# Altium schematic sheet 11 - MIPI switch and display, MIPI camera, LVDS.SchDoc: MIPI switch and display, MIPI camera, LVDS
size A3; PageSetup: Record=PageOptions¦CenterHorizontal=True¦CenterVertical=True¦PrintScale=0.70¦XCorrection=1.00¦YCorrection=1.00¦PrintKind=0¦BorderSize=5000000¦LeftOffset=0¦BottomOffset=0¦Orientation=2¦PaperLength=4200¦PaperWidth=2970¦Scale=100¦PaperSource=7¦PrintQuality=600¦MediaType=1¦DitherType=10¦PaperKind=A4¦PrintScaleMode=1; Author: Juan Anzola; SheetNumber: 11; SheetTotal: 20
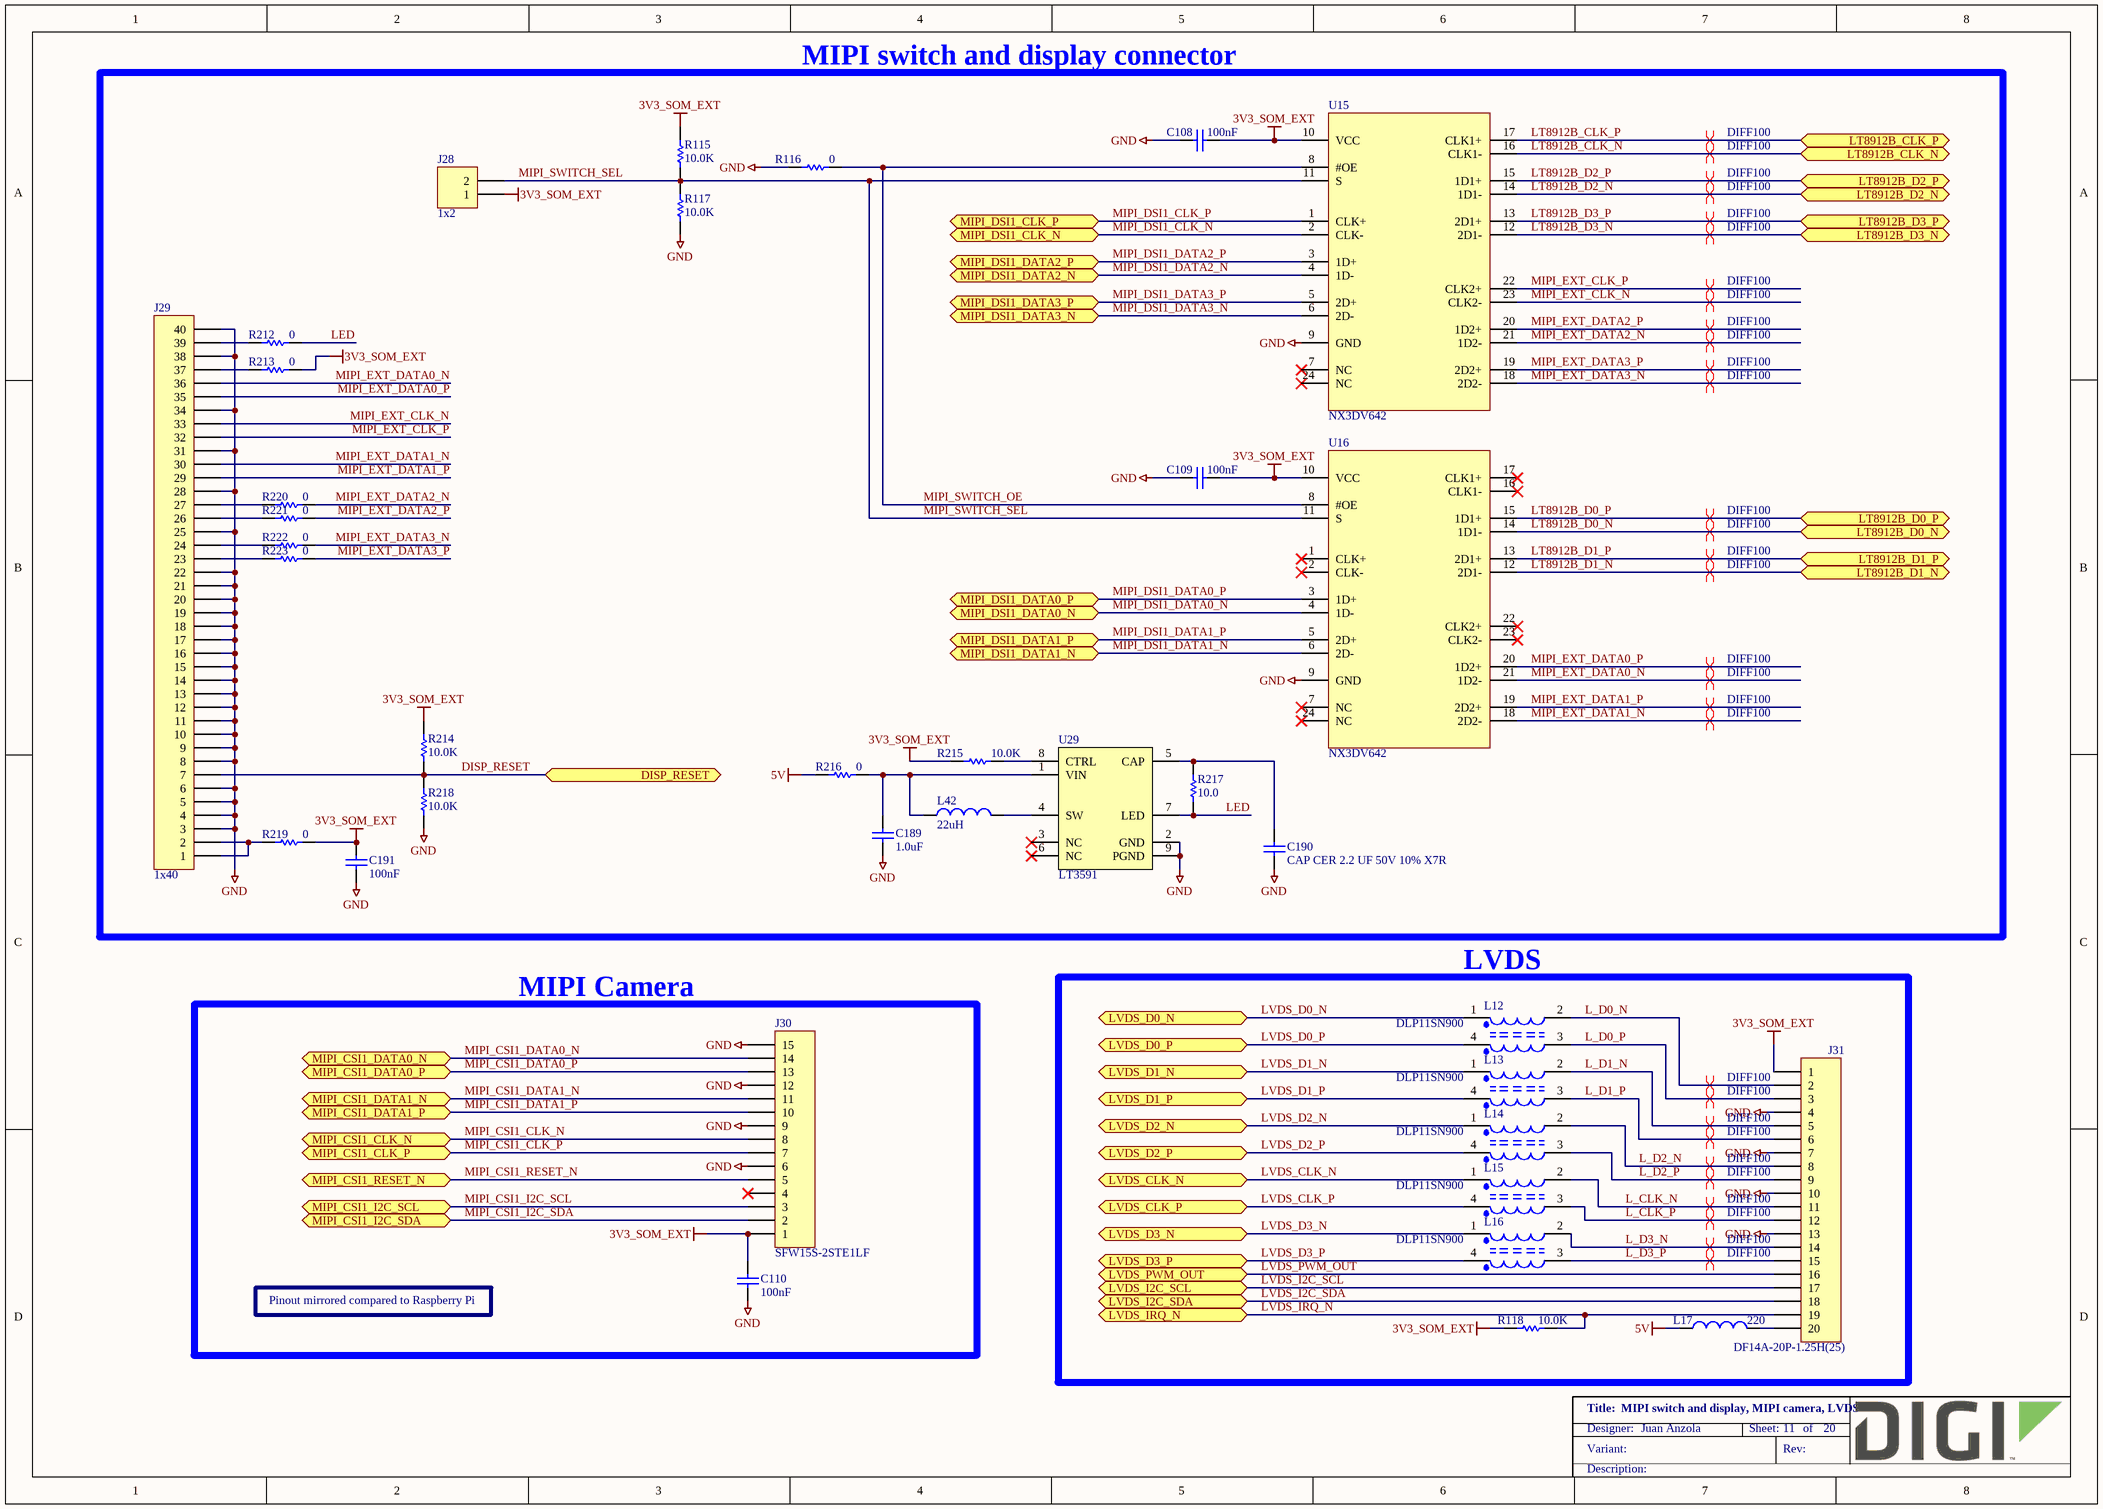
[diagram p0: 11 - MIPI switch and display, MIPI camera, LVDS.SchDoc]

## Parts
C108  100nF  [CAPC1005X55N]
C109  100nF  [CAPC1005X55N]
C110  100nF  [CAPC1005X55N]
C189  1.0uF  [CAPC1005X55N]
C190  CAP CER 2.2 UF 50V 10% X7R  [CAPC3225X250N]
C191  100nF  [CAPC1005X55N]
J28  1x2  [FCI_68002-102HLF]
J29  1x40  [OMRON_XF2M-4015-1A]
J30  SFW15S-2STE1LF  [FCI_SFW15S-2STE1LF]
J31  DF14A-20P-1.25H(25)  [HIROSE_DF14A-20P-1.25H]
L12  DLP11SN900  [FIL_DLP11S]
L13  DLP11SN900  [FIL_DLP11S]
L14  DLP11SN900  [FIL_DLP11S]
L15  DLP11SN900  [FIL_DLP11S]
L16  DLP11SN900  [FIL_DLP11S]
L17  220  [INDC2013X110N]
L42  22uH  [IND_NR4018T220M]
R115  10.0K  [RESC1005X40N]
R116  0  [RESC1609X55N]
R117  10.0K  [RESC1005X40N]
R118  10.0K  [RESC1005X40N]
R212  0  [RESC1005X40N]
R213  0  [RESC1005X40N]
R214  10.0K  [RESC1005X40N]
R215  10.0K  [RESC1005X40N]
R216  0  [RESC1005X40N]
R217  10.0  [RESC1005X40N]
R218  10.0K  [RESC1005X40N]
R219  0  [RESC1005X40N]
R220  0  [RESC1005X40N]
R221  0  [RESC1005X40N]
R222  0  [RESC1005X40N]
R223  0  [RESC1005X40N]
U15  NX3DV642  [QFN40P340X250X50-24N]
U16  NX3DV642  [QFN40P340X250X50-24N]
U29  LT3591  [SON50P300X200X80-9T56X215N]

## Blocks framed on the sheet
MIPI switch and display connector: C108 C109 C189-C191 J28 J29 L42 R115-R117 R212-R223 U15 U16 U29
LVDS: J31 L12-L17 R118
MIPI Camera: C110 J30

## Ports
DISP_RESET (bidir), LT8912B_CLK_N (bidir), LT8912B_CLK_P (bidir), LT8912B_D0_N (bidir), LT8912B_D0_P (bidir), LT8912B_D1_N (bidir), LT8912B_D1_P (bidir), LT8912B_D2_N (bidir), LT8912B_D2_P (bidir), LT8912B_D3_N (bidir), LT8912B_D3_P (bidir), LVDS_CLK_N (bidir), LVDS_CLK_P (bidir), LVDS_D0_N (bidir), LVDS_D0_P (bidir), LVDS_D1_N (bidir), LVDS_D1_P (bidir), LVDS_D2_N (bidir), LVDS_D2_P (bidir), LVDS_D3_N (bidir), LVDS_D3_P (bidir), LVDS_I2C_SCL (bidir), LVDS_I2C_SDA (bidir), LVDS_IRQ_N (bidir), LVDS_PWM_OUT (bidir), MIPI_CSI1_CLK_N (bidir), MIPI_CSI1_CLK_P (bidir), MIPI_CSI1_DATA0_N (bidir), MIPI_CSI1_DATA0_P (bidir), MIPI_CSI1_DATA1_N (bidir), MIPI_CSI1_DATA1_P (bidir), MIPI_CSI1_I2C_SCL (bidir), MIPI_CSI1_I2C_SDA (bidir), MIPI_CSI1_RESET_N (bidir), MIPI_DSI1_CLK_N (bidir), MIPI_DSI1_CLK_P (bidir), MIPI_DSI1_DATA0_N (bidir), MIPI_DSI1_DATA0_P (bidir), MIPI_DSI1_DATA1_N (bidir), MIPI_DSI1_DATA1_P (bidir), MIPI_DSI1_DATA2_N (bidir), MIPI_DSI1_DATA2_P (bidir), MIPI_DSI1_DATA3_N (bidir), MIPI_DSI1_DATA3_P (bidir)

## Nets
3V3_SOM_EXT: C108.1 C109.1 C110.2 C191.2 J28.1 J30.1 J31.1 R115.1 R118.1 R213.2 R214.1 R215.1 R219.2 U15.10(VCC) U16.10(VCC)
5V: L17.1 R216.1
GND: C108.2 C109.2 C110.1 C189.1 C190.1 C191.1 J29.3 J29.4 J29.5 J29.6 J29.8 J29.9 J29.10 J29.11 J29.12 J29.13 J29.14 J29.15 J29.16 J29.17 J29.18 J29.19 J29.20 J29.21 J29.22 J29.25 J29.28 J29.31 J29.34 J29.38 J29.40 J30.6 J30.9 J30.12 J30.15 J31.4 J31.7 J31.10 J31.13 R116.1 R117.2 R218.2 U15.9(GND) U16.9(GND) U29.2(GND) U29.9(PGND)
DISP_RESET: J29.7 R214.2 R218.1 ; port DISP_RESET
L_CLK_N: J31.11 L15.2
L_CLK_P: J31.12 L15.3
L_D0_N: J31.2 L12.2
L_D0_P: J31.3 L12.3
L_D1_N: J31.5 L13.2
L_D1_P: J31.6 L13.3
L_D2_N: J31.8 L14.2
L_D2_P: J31.9 L14.3
L_D3_N: J31.14 L16.2
L_D3_P: J31.15 L16.3
LED: R212.2 R217.1 U29.7(LED)
LT8912B_CLK_N: U15.16(CLK1-) ; port LT8912B_CLK_N
LT8912B_CLK_P: U15.17(CLK1+) ; port LT8912B_CLK_P
LT8912B_D0_N: U16.14(1D1-) ; port LT8912B_D0_N
LT8912B_D0_P: U16.15(1D1+) ; port LT8912B_D0_P
LT8912B_D1_N: U16.12(2D1-) ; port LT8912B_D1_N
LT8912B_D1_P: U16.13(2D1+) ; port LT8912B_D1_P
LT8912B_D2_N: U15.14(1D1-) ; port LT8912B_D2_N
LT8912B_D2_P: U15.15(1D1+) ; port LT8912B_D2_P
LT8912B_D3_N: U15.12(2D1-) ; port LT8912B_D3_N
LT8912B_D3_P: U15.13(2D1+) ; port LT8912B_D3_P
LVDS_CLK_N: L15.1 ; port LVDS_CLK_N
LVDS_CLK_P: L15.4 ; port LVDS_CLK_P
LVDS_D0_N: L12.1 ; port LVDS_D0_N
LVDS_D0_P: L12.4 ; port LVDS_D0_P
LVDS_D1_N: L13.1 ; port LVDS_D1_N
LVDS_D1_P: L13.4 ; port LVDS_D1_P
LVDS_D2_N: L14.1 ; port LVDS_D2_N
LVDS_D2_P: L14.4 ; port LVDS_D2_P
LVDS_D3_N: L16.1 ; port LVDS_D3_N
LVDS_D3_P: L16.4 ; port LVDS_D3_P
LVDS_I2C_SCL: J31.17 ; port LVDS_I2C_SCL
LVDS_I2C_SDA: J31.18 ; port LVDS_I2C_SDA
LVDS_IRQ_N: J31.19 R118.2 ; port LVDS_IRQ_N
LVDS_PWM_OUT: J31.16 ; port LVDS_PWM_OUT
MIPI_CSI1_CLK_N: J30.8 ; port MIPI_CSI1_CLK_N
MIPI_CSI1_CLK_P: J30.7 ; port MIPI_CSI1_CLK_P
MIPI_CSI1_DATA0_N: J30.14 ; port MIPI_CSI1_DATA0_N
MIPI_CSI1_DATA0_P: J30.13 ; port MIPI_CSI1_DATA0_P
MIPI_CSI1_DATA1_N: J30.11 ; port MIPI_CSI1_DATA1_N
MIPI_CSI1_DATA1_P: J30.10 ; port MIPI_CSI1_DATA1_P
MIPI_CSI1_I2C_SCL: J30.3 ; port MIPI_CSI1_I2C_SCL
MIPI_CSI1_I2C_SDA: J30.2 ; port MIPI_CSI1_I2C_SDA
MIPI_CSI1_RESET_N: J30.5 ; port MIPI_CSI1_RESET_N
MIPI_DSI1_CLK_N: U15.2(CLK-) ; port MIPI_DSI1_CLK_N
MIPI_DSI1_CLK_P: U15.1(CLK+) ; port MIPI_DSI1_CLK_P
MIPI_DSI1_DATA0_N: U16.4(1D-) ; port MIPI_DSI1_DATA0_N
MIPI_DSI1_DATA0_P: U16.3(1D+) ; port MIPI_DSI1_DATA0_P
MIPI_DSI1_DATA1_N: U16.6(2D-) ; port MIPI_DSI1_DATA1_N
MIPI_DSI1_DATA1_P: U16.5(2D+) ; port MIPI_DSI1_DATA1_P
MIPI_DSI1_DATA2_N: U15.4(1D-) ; port MIPI_DSI1_DATA2_N
MIPI_DSI1_DATA2_P: U15.3(1D+) ; port MIPI_DSI1_DATA2_P
MIPI_DSI1_DATA3_N: U15.6(2D-) ; port MIPI_DSI1_DATA3_N
MIPI_DSI1_DATA3_P: U15.5(2D+) ; port MIPI_DSI1_DATA3_P
MIPI_EXT_CLK_N: J29.33 U15.23(CLK2-)
MIPI_EXT_CLK_P: J29.32 U15.22(CLK2+)
MIPI_EXT_DATA0_N: J29.36 U16.21(1D2-)
MIPI_EXT_DATA0_P: J29.35 U16.20(1D2+)
MIPI_EXT_DATA1_N: J29.30 U16.18(2D2-)
MIPI_EXT_DATA1_P: J29.29 U16.19(2D2+)
MIPI_EXT_DATA2_N: R220.2 U15.21(1D2-)
MIPI_EXT_DATA2_P: R221.2 U15.20(1D2+)
MIPI_EXT_DATA3_N: R222.2 U15.18(2D2-)
MIPI_EXT_DATA3_P: R223.2 U15.19(2D2+)
MIPI_SWITCH_OE: R116.2 U15.8(#OE) U16.8(#OE)
MIPI_SWITCH_SEL: J28.2 R115.2 R117.1 U15.11(S) U16.11(S)
NetC189_2: C189.2 L42.1 R216.2 U29.1(VIN)
NetC190_2: C190.2 R217.2 U29.5(CAP)
NetJ29_1: J29.1 J29.2 R219.1
NetJ29_23: J29.23 R223.1
NetJ29_24: J29.24 R222.1
NetJ29_26: J29.26 R221.1
NetJ29_27: J29.27 R220.1
NetJ29_37: J29.37 R213.1
NetJ29_39: J29.39 R212.1
NetJ31_20: J31.20 L17.2
NetL42_2: L42.2 U29.4(SW)
NetR215_2: R215.2 U29.8(CTRL)

Not connected (* = marked no-connect by the designer): J30 4*; U15 7(NC)* 24(NC)*; U16 1(CLK+)* 2(CLK-)* 7(NC)* 16(CLK1-)* 17(CLK1+)* 22(CLK2+)* 23(CLK2-)* 24(NC)*; U29 3(NC)* 6(NC)*

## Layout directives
differential pair; net class DIFF100; differential pair class DIFF100: L_CLK_N, L_CLK_P, L_D0_N, L_D0_P, L_D1_N, L_D1_P, L_D2_N, L_D2_P, L_D3_N, L_D3_P, LT8912B_CLK_N, LT8912B_CLK_P, LT8912B_D0_N, LT8912B_D0_P, LT8912B_D1_N, LT8912B_D1_P, LT8912B_D2_N, LT8912B_D2_P, LT8912B_D3_N, LT8912B_D3_P, MIPI_EXT_CLK_N, MIPI_EXT_CLK_P, MIPI_EXT_DATA0_N, MIPI_EXT_DATA0_P, MIPI_EXT_DATA1_N, MIPI_EXT_DATA1_P, MIPI_EXT_DATA2_N, MIPI_EXT_DATA2_P, MIPI_EXT_DATA3_N, MIPI_EXT_DATA3_P

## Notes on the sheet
- Pinout mirrored compared to Raspberry Pi

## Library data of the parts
C108-C110 = 1000006: CAP 100nF 16V 10% X7R 0402; Part_Type: Capacitor; Manufacturer: Murata; Manufacturer_Part_Number: GRM155R71C104KA88D; Digi_PN: 14050552; Component_Life_Cycle_State: CAD Reviewed; Area: 0,95; Project: KITT; Tolerance: 10
C189 = 1001167: CAP CER 1UF 10V 10% X5R 0402; Part_Type: Capacitor; Manufacturer: Murata; Manufacturer_Part_Number: GRM155R61A105KE15D; Digi_PN: 14050399; Component_Life_Cycle_State: Reviewed; Area: 0,95
C190 = 1002042: 2.2µF ±10% 50V X7R Ceramic Capacitor -55°C ~ 125°C Surface Mount, MLCC 1210 (3225 Metric) 0.126" L x 0.098" W (3.20mm x 2.50mm); Manufacturer: AVX; Manufacturer_Part_Number: 12105C225KAT2A; Digi_PN: 14050578; Component_Life_Cycle_State: Created; Area: 8
C191 = 1000006: CAP 100nF 16V 10% X7R 0402; Part_Type: Capacitor; Manufacturer: Murata; Manufacturer_Part_Number: GRM155R71C104KA88D; Digi_PN: 14050552; Component_Life_Cycle_State: CAD Reviewed; Area: 0,95; Tolerance: 10
J28 = 1001128: CONN HEADER 2POS .100" SGL GOLD; Part_Type: Connector; Manufacturer: Samtec; Manufacturer_Part_Number: TSW-102-07-G-S; Digi_PN: 00120002; Component_Life_Cycle_State: Reviewed; Area: 12,9032
J29 = 1001144: CONN FPC 40POS 0.5MM PITCH SMD; Part_Type: Connector; Manufacturer: Omron; Manufacturer_Part_Number: XF2M-4015-1A; Digi_PN: 18000676; Component_Life_Cycle_State: Reviewed; Area: 117,5
J30 = 1001866: CONN FFC FPC VERT 15POS 1MM SMD; Part_Type: Connector; Manufacturer: FCI; Digi_PN: 18000730; Component_Life_Cycle_State: Reviewed; Area: 128,76; Project: CCiMX6 SBC MFG TEST BOARD
J31 = 1001132: CONN HEADER 20POS 1.25MM R/A SMD; Part_Type: Connector; Manufacturer: Hirose; Digi_PN: 18050231; Component_Life_Cycle_State: Reviewed; Area: 206.34; Project: CCWMX6_SBC board
L12-L16 = 1001014: CHOKE COIL COMMON MODE 150MA SMD; Part_Type: Inductor; Manufacturer: Murata; Manufacturer_Part_Number: DLP11SN900HL2L; Component_Life_Cycle_State: Reviewed; Area: 3.94; Project: ResMed RF Test Interface Board; Digi_PN: 21000531
L17 = 1001174: FERRITE BEAD 220 OHM 2.0A 0805; Manufacturer: Wurth Electronics Inc; Manufacturer_Part_Number: 742792022; Digi_PN: 21000146; Component_Life_Cycle_State: Reviewed; Area: 4.24; Project: CCWMX6_SBC board
L42 = 1002050: FIXED IND 22UH 590MA 432 MOHM; Manufacturer: Taiyo Yuden; Manufacturer_Part_Number: NR4018T220M; Digi_PN: 21000545; Component_Life_Cycle_State: Created; Area: 16
R115 R117 R215 = 1000537: RES 10.0K OHM 1/10W 1% 0402 SMD; Part_Type: Resistor; Manufacturer: Panasonic - ECG; Manufacturer_Part_Number: ERJ-2RKF1002X; Digi_PN: 13051084; Component_Life_Cycle_State: CAD Reviewed; Area: 0,95; Power_WV_SRF: 100
R116 = 1000208: RES 0.0 OHM 1/10W 0603; Part_Type: Resistor; Manufacturer: Panasonic - ECG; Manufacturer_Part_Number: ERJ-3GEY0R00V; Note: 13051103 = Digi No. for GE WDNU; Digi_PN: 13050568; Component_Life_Cycle_State: Reviewed; Area: 2,5; Voltage: 75V
R118 R214 R218 = 1000537: RES 10.0K OHM 1/10W 1% 0402 SMD; Part_Type: Resistor; Manufacturer: Panasonic - ECG; Manufacturer_Part_Number: ERJ-2RKF1002X; Component_Life_Cycle_State: CAD Reviewed; Area: 0.95; Project: KITT; Power_WV_SRF: 100; Digi_PN: 13051084
R212 R213 R219 = 1000076: RES 0.0 OHM 1/10W 0402 SMD; Part_Type: Resistor; Manufacturer: Panasonic - ECG; Manufacturer_Part_Number: ERJ-2GE0R00X; Component_Life_Cycle_State: Proven; Area: 0.95; Project: Adjustable Foundation; Power_WV_SRF: 10; Digi_PN: 13050387
R216 = 1000076: RES 0.0 OHM 1/10W 0402 SMD; Part_Type: Resistor; Manufacturer: Panasonic - ECG; Manufacturer_Part_Number: ERJ-2GE0R00X; Digi_PN: 13050387; Component_Life_Cycle_State: Proven; Area: 0,95; Project: Adjustable Foundation; Power_WV_SRF: 10
R217 = 1000711: RES 10.0 OHM 1/10W 1% 0402 SMD; Part_Type: Resistor; Manufacturer: Panasonic - ECG; Manufacturer_Part_Number: ERJ-2RKF10R0X; Digi_PN: 13051067; Component_Life_Cycle_State: Reviewed; Area: 0,95; Power_WV_SRF: 100
R220-R223 = 1000076: RES 0.0 OHM 1/10W 0402 SMD; Part_Type: Resistor; Manufacturer: Panasonic - ECG; Manufacturer_Part_Number: ERJ-2GE0R00X; Digi_PN: 13050387; Component_Life_Cycle_State: Proven; Area: 0,95; Power_WV_SRF: 10
U15 U16 = 1002697: IC SWITCH TPDT DIFF XQFN24; Manufacturer: NXP Semiconductors; Digi_PN: 16000171; Component_Life_Cycle_State: Reviewed; Area: 17,35
U29 = 1002036: LED Driver IC 1 Output DC DC Regulator Step-Up (Boost) PWM Dimming 500mA (Switch) 8-DFN (3x2); Manufacturer: Linear Technology; Manufacturer_Part_Number: LT3591EDDB#TRMPBF; Digi_PN: 17050521; Component_Life_Cycle_State: Created; Area: 6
